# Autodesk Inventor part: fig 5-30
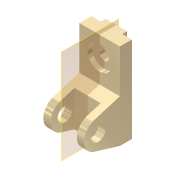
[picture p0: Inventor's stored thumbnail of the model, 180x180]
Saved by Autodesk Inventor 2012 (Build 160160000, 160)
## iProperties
Shininess: 65.0
Angle Display Precision: 2
Document Length Units: 11269
Document Angle Units: 11279
Document Time Units: 11290
Document Mass Units: 11283
Document Length Units Precision: 3
Document Angle Units Precision: 2
Created: 2001-11
Part Number: fig 5-30
Document SubType Name: Modeling
Designer: Renu Muthoo
Density: 1 g/cm^3
Material: Default
Density: 0.0
Volumn: 0.0
Area: 0.0
PropertySet Name: Model Information
Control State: 0
Master: False
Checked Out: False
Author: Renu Muthoo
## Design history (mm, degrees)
node "Sketch1"
sketch "Sketch2"
  geometry: L1 (33.257, 104.664)-(33.257, -75.336); L2 (33.257, -75.336)-(8.257, -75.336); L3 (8.257, -75.336)-(-45.451, -59.045); L4 (-45.451, -1.628)-(8.257, 14.664); L5 (8.257, 14.664)-(8.257, 104.664); L6 (8.257, 104.664)-(33.257, 104.664); C1 r 15 at (-36.743, -30.336); A1 r 30 centre (-36.743, -30.336) between (-45.451, -1.628) and (-45.451, -59.045)
  constraints: 12 end point, 2 centre point, 2 equal length, 2 parallel, 2 point on circle, 2 tangent, 1 coincident, 1 perpendicular, 1 vertical
  dimensions: "d0" = 180 distance of L1.start L1.end; "d1" = 30 radius of A1; "d2" = 25 distance of L5.end L1.start; "d3" = 45 distance from line of L2 A1.centre; "d4" = 70 distance from line of L1 A1.centre; "d5" = 30 diameter of C1
extrude "Extrusion1" new body sketch "Sketch2" distance "d6" = 85; taper "d7" = 0 deg
workplane "Work Plane1"
sketch "Sketch3"
  geometry: L1 (15, 62.364)-(70, 62.364); L2 (70, 62.364)-(70, -52.386); L3 (70, -52.386)-(15, -52.386); L4 (15, -52.386)-(15, 62.364); L5 (0, -45)-(0, -28.708) reference
  constraints: 8 end point, 2 parallel, 1 horizontal, 1 perpendicular
  dimensions: "d8" = 55 distance of L1.start L1.end; "d9" = 15 distance between parallel lines of L5 L4
extrude "Extrusion2" cut sketch "Sketch3" distance "d10" = 50; taper "d11" = 0 deg
sketch "Sketch4"
  geometry: L1 (0, 25)-(85, 25) reference; L2 (0, 0)-(0, 25) reference; L3 (20, 25)-(65, 25); L4 (65, 25)-(65, 35); L5 (65, 35)-(20, 35); L6 (20, 35)-(20, 25)
  constraints: 8 end point, 2 parallel, 1 horizontal, 1 perpendicular, 1 point on line
  dimensions: "d12" = 45 distance of L4.end L5.end; "d13" = 10 distance of L3.end L4.end; "d14" = 20 distance between parallel lines of L2 L6
extrude "Extrusion3" join sketch "Sketch4" stored distance "d15" = 50; taper "d16" = 0 deg
sketch "Sketch5"
  geometry: L1 (85, 0)-(85, 90) reference; L2 (0, 90)-(85, 90) reference; 1 further point
  dimensions: "d17" = 42 distance from line of L2 point (42.5, 48); "d18" = 42.5 distance from line of L1 point (42.5, 48)
hole "Hole1" sketch "Sketch5" at (42.5, 48) diameter "d19" = 20; stored, may be unused: countersink angle "d23" = 82 deg, drill point angle "d25" = 118 deg; dims "d20" = 6, "d21" = 50, "d22" = 10, "d24" = 8
workplane "Work Plane5"
body "Solid1"
